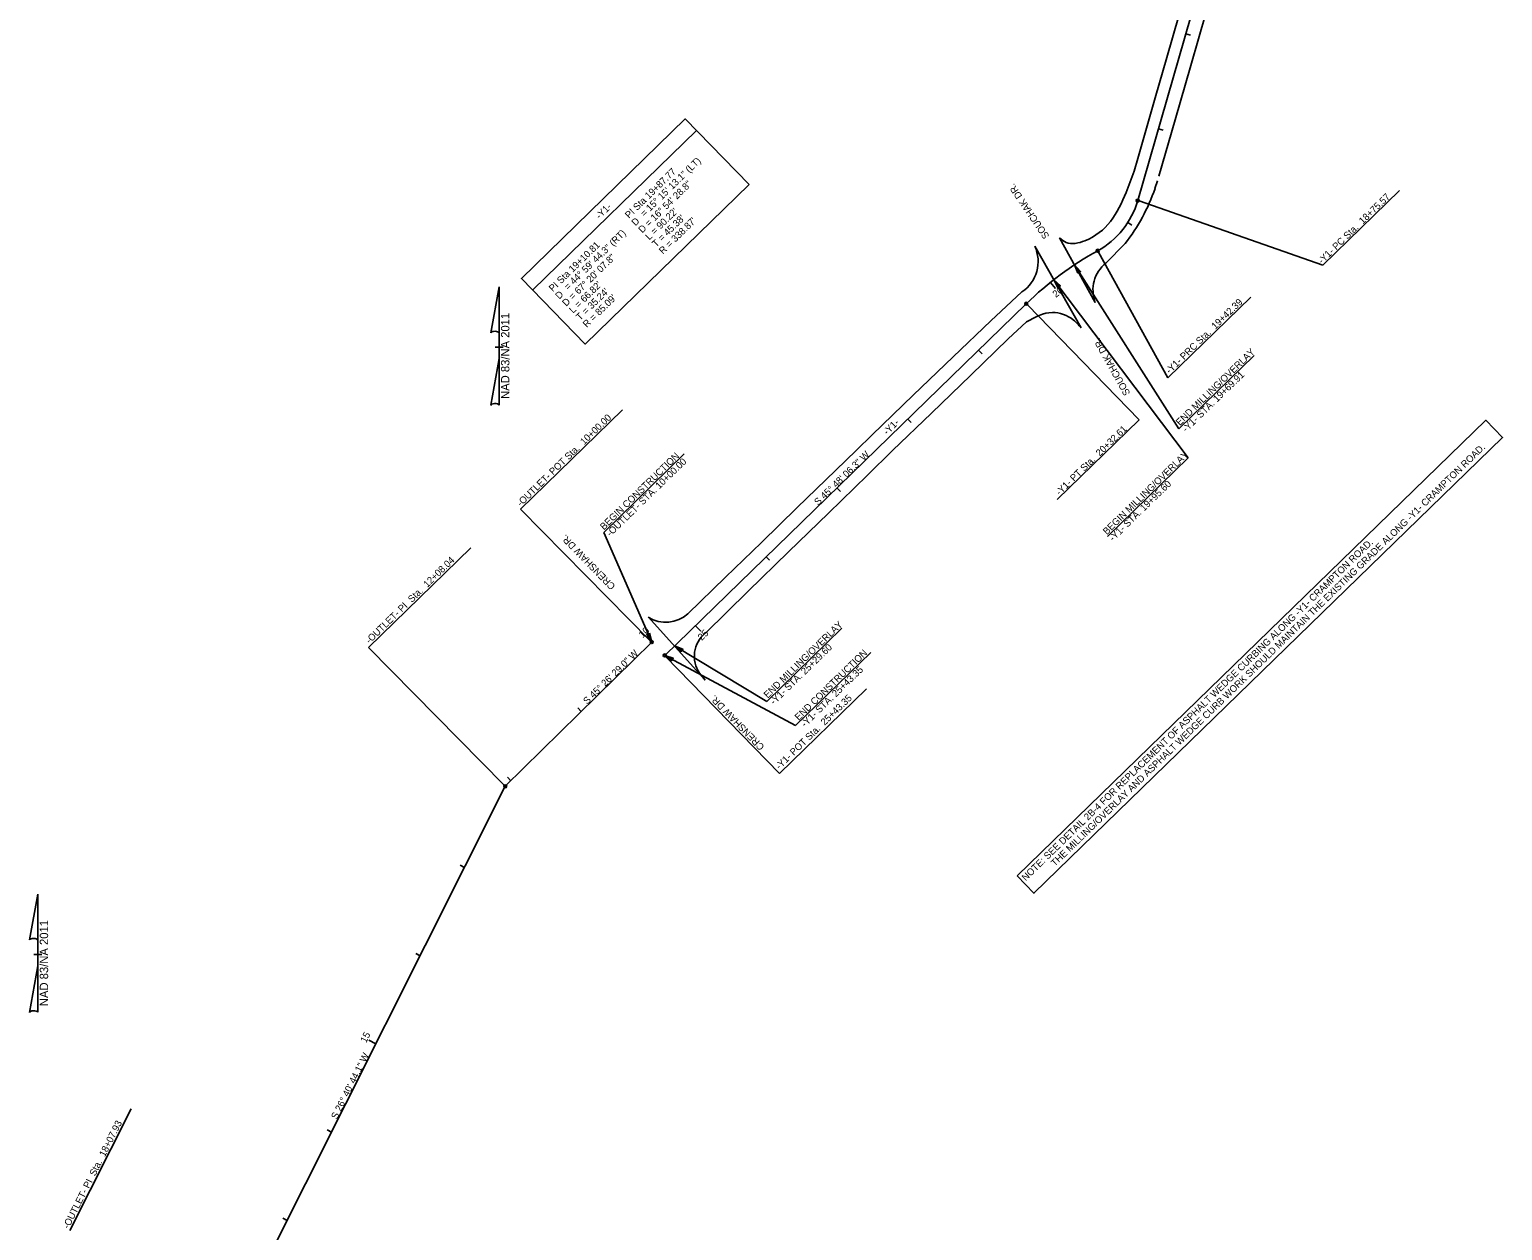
# Model space of a CAD drawing. Extents: x 2010838 to 2015151, y 441905 to 447792.
# Drawn here: x 2011071 to 2012563, y 443073 to 444289 of the extents above; entities that cross this region are included whole.
import ezdxf

# ---------------------------------------------------------------- set-up
doc = ezdxf.new("R2010")
doc.units = 0
for name, color, linetype in [('$AUDIT_BAD_LAYER1', 7, 'Continuous'), ('1-BUFFER', 7, 'Continuous'), ('B - Border Text', 7, 'Continuous'), ('C-Building', 7, 'Continuous'), ('C-EOP 1', 7, 'Continuous'), ('C-Grave Plots', 7, 'Continuous'), ('C-SHBD-TEXT', 7, 'Continuous'), ('CLRD', 7, 'Continuous'), ('Cont-10-Lidar', 7, 'Continuous'), ('Cont-2-Lidar', 7, 'Continuous'), ('Default_10ft_LIDAR_Contou', 7, 'Continuous'), ('Default_2FT_LIDAR_Contour', 7, 'Continuous'), ('Default_Parcels', 7, 'Continuous'), ('s-Existing Major', 7, 'Continuous'), ('S-Existing Minor', 7, 'Continuous'), ('S-overhead electric', 7, 'Continuous')]:
    doc.layers.add(name, color=color, linetype=linetype)

msp = doc.modelspace()

# ---------------------------------------------------------------- linework, layer by layer
at = {"layer": '$AUDIT_BAD_LAYER1'}
for p, q in [((2012370.9, 444732.8), (2012193.3, 444115.9)), ((2012080.5, 444011.4), (2011714.4, 443655.3))]:
    msp.add_line(p, q, dxfattribs=at)
for centre, radius, start, end in [((2012111.6, 444139.5), 85.1, 298.9446, 343.9402), ((2012316.8, 443768.5), 338.9, 118.9446, 134.1983)]:
    msp.add_arc(centre, radius, start, end, dxfattribs=at)
at = {"layer": '1-BUFFER'}
msp.add_lwpolyline([(2012071.2, 443432), (2012545.7, 443893.4), (2012562.7, 443875.9), (2012088.2, 443414.5)], close=True, dxfattribs=at)
at = {"layer": 'B - Border Text'}
for p, q in [((2011538.5, 443982.1), (2011546.7, 444028.4)), ((2011546.7, 444028.4), (2011546.7, 444028.4)), ((2011546.7, 444028.4), (2011546.7, 444028.4)), ((2011546.7, 444028.4), (2011546.7, 443980.6)), ((2011546.7, 443955.8), (2011546.7, 443982)), ((2011546.7, 443980.6), (2011546.7, 443982)), ((2011546.3, 443967.4), (2011542.7, 443967.4)), ((2011542.7, 443967.4), (2011542.7, 443967.4)), ((2011542.8, 443967.4), (2011550.8, 443967.4)), ((2011546.7, 443955.8), (2011538.4, 443908.6)), ((2011546.8, 443908.8), (2011546.7, 443955.8)), ((2011071.4, 443367.3), (2011079.6, 443413.6)), ((2011079.6, 443413.6), (2011079.6, 443413.6)), ((2011079.6, 443413.6), (2011079.6, 443413.6)), ((2011079.6, 443413.6), (2011079.6, 443365.8)), ((2011079.6, 443341), (2011079.6, 443367.2)), ((2011079.6, 443365.8), (2011079.6, 443367.2)), ((2011079.2, 443352.6), (2011075.6, 443352.6)), ((2011075.6, 443352.6), (2011075.6, 443352.6)), ((2011075.7, 443352.6), (2011083.7, 443352.6)), ((2011079.6, 443341), (2011071.3, 443293.8)), ((2011079.7, 443294), (2011079.6, 443341))]:
    msp.add_line(p, q, dxfattribs=at)
for centre, start_param, end_param in [((2011542.6, 443981.6), 0.216388, 2.908219), ((2011542.6, 443908.4), 0.201328, 3.141593), ((2011075.5, 443366.8), 0.216388, 2.908219), ((2011075.5, 443293.6), 0.201328, 3.141593)]:
    msp.add_ellipse(centre, major_axis=(4.23, -0.03), ratio=0.461098, start_param=start_param, end_param=end_param, dxfattribs=at)
at = {"layer": 'C-Building'}
for p, q in [((2012241.9, 444284.6), (2012246.7, 444283.2)), ((2012214.3, 444188.5), (2012219.1, 444187.2)), ((2012183.3, 444093.7), (2012187.5, 444091)), ((2012032.2, 443964.4), (2012035.7, 443960.8)), ((2011960.5, 443894.7), (2011964, 443891.1)), ((2011888.8, 443825), (2011892.3, 443821.4)), ((2011817.1, 443755.3), (2011820.6, 443751.7)), ((2011630, 443598.6), (2011626.5, 443602.2)), ((2011558.8, 443528.5), (2011555.2, 443532)), ((2011511.7, 443440.7), (2011507.3, 443442.9)), ((2011466.8, 443351.3), (2011462.4, 443353.6)), ((2011377, 443172.6), (2011372.6, 443174.9)), ((2011332.1, 443083.3), (2011327.7, 443085.5))]:
    msp.add_line(p, q, dxfattribs=at)
at = {"layer": 'C-EOP 1'}
for p, q in [((2012105, 444033), (2012110, 444026.7)), ((2011745.4, 443685.6), (2011751, 443679.8)), ((2011701.3, 443668.8), (2011695.6, 443674.5)), ((2011421.9, 443262), (2011414.8, 443265.6))]:
    msp.add_line(p, q, dxfattribs=at)
at = {"layer": 'C-SHBD-TEXT'}
for p, q in [((2012089.1, 444069.7), (2012136.1, 443987)), ((2012114, 444078.1), (2012150.3, 444012.8)), ((2011755.5, 443630.4), (2011697.9, 443694))]:
    msp.add_line(p, q, dxfattribs=at)
at = {"layer": 'CLRD'}
for p, q in [((2012370.9, 444732.8), (2012193.3, 444115.9)), ((2012080.5, 444011.4), (2011714.4, 443655.3)), ((2011701.3, 443668.8), (2011553, 443522.8)), ((2011553, 443522.8), (2011283.7, 442986.8))]:
    msp.add_line(p, q, dxfattribs=at)
for centre, radius, start, end in [((2012111.6, 444139.5), 85.1, 298.9446, 343.9402), ((2012316.8, 443768.5), 338.9, 118.9446, 134.1983)]:
    msp.add_arc(centre, radius, start, end, dxfattribs=at)
at = {"layer": 'Default_10ft_LIDAR_Contou'}
for p, q in [((2012380.9, 444050.5), (2012458.4, 444125.9)), ((2012194.8, 444115.5), (2012380.9, 444050.5)), ((2012153.5, 444063.7), (2012223.9, 443936.4)), ((2012081.6, 444010.3), (2012194.8, 443893.8)), ((2012307.9, 444018), (2012223.9, 443936.4)), ((2011568.6, 443803.5), (2011671.8, 443903.9)), ((2012111.8, 443813.1), (2012194.8, 443893.8)), ((2011700.2, 443669.9), (2011568.6, 443803.5)), ((2011414.6, 443663.4), (2011518.2, 443764.2)), ((2011552, 443523.9), (2011414.6, 443663.4)), ((2011715.4, 443654.3), (2011830.5, 443535.8)), ((2011830.5, 443535.8), (2011918.6, 443621.4)), ((2011112.2, 443073), (2011174.2, 443196.2))]:
    msp.add_line(p, q, dxfattribs=at)
for centre in [(2012193.3, 444115.9), (2012152.8, 444065), (2012080.5, 444011.4), (2011701.3, 443668.8), (2011714.4, 443655.3), (2011553, 443522.8)]:
    msp.add_circle(centre, 1.5, dxfattribs=at)
at = {"layer": 'Default_Parcels'}
msp.add_line((2011580.8, 444025.4), (2011746.7, 444186.7), dxfattribs=at)
msp.add_lwpolyline([(2011800, 444132), (2011634, 443970.6), (2011569.4, 444037.1), (2011735.3, 444198.5)], close=True, dxfattribs=at)
at = {"layer": 's-Existing Major'}
for points in [[(2012132.8, 444042.3), (2012129.2, 444050.7), (2012135.5, 444043.9), (2012133.5, 444044.1)], [(2012112.6, 444027.6), (2012108.4, 444035.7), (2012115.1, 444029.4), (2012113.2, 444029.4)], [(2011699.1, 443677.7), (2011701.3, 443668.8), (2011696.2, 443676.5), (2011698.1, 443676)], [(2011731.1, 443659), (2011724.2, 443664.9), (2011732.8, 443661.6), (2011731, 443660.9)], [(2011721.5, 443649.7), (2011714.4, 443655.3), (2011723.1, 443652.5), (2011721.3, 443651.6)]]:
    msp.add_lwpolyline(points, close=True, dxfattribs=at)
at = {"layer": 'S-Existing Minor'}
for p, q in [((2012129.2, 444050.7), (2012235, 443884.9)), ((2012108.4, 444035.7), (2012244.5, 443855.5)), ((2012235, 443884.9), (2012311.2, 443959)), ((2011652.7, 443779.9), (2011734.3, 443859.3)), ((2012162.6, 443775.9), (2012244.5, 443855.5)), ((2011701.3, 443668.8), (2011652.7, 443779.9)), ((2011817.7, 443608.8), (2011893.9, 443683)), ((2011724.2, 443664.9), (2011817.7, 443608.8)), ((2011714.4, 443655.3), (2011846.9, 443584.2)), ((2011846.9, 443584.2), (2011923.1, 443658.3))]:
    msp.add_line(p, q, dxfattribs=at)
at = {"layer": 'S-overhead electric'}
for p, q in [((2012193.3, 444158.4), (2012189.6, 444145.5)), ((2012189.6, 444145.5), (2012181.8, 444124.2)), ((2012210.8, 444128.1), (2012213.4, 444136)), ((2012136.1, 443987), (2012089.1, 444069.7)), ((2012114, 444078.1), (2012150.3, 444012.8)), ((2012161.2, 444052.6), (2012180.6, 444072.3)), ((2011908.6, 443863.2), (2011924.6, 443878.6)), ((2011919.7, 443837.8), (2011944.9, 443862.7)), ((2011755.5, 443630.4), (2011697.9, 443694)), ((2011749.8, 443637.2), (2011755.5, 443630.4))]:
    msp.add_line(p, q, dxfattribs=at)
for points in [[(2012214.8, 444140.6), (2012231.4, 444197.5), (2012247, 444252.5), (2012262.5, 444306.6), (2012277.8, 444361), (2012294.5, 444419.1), (2012308.1, 444465.5), (2012323.9, 444521.6), (2012337.3, 444572.2), (2012352.2, 444622.1), (2012368.4, 444674.4)], [(2012298.3, 444525.6), (2012284.2, 444475.2), (2012267.7, 444418.9), (2012251.3, 444361.5), (2012234.9, 444303), (2012222.7, 444260.8), (2012211.1, 444219.8), (2012193.3, 444158.4)], [(2012076.1, 444023.4), (2012044.6, 443994.1), (2012006.6, 443957.8), (2011966.1, 443918.8), (2011924.6, 443878.6)], [(2011944.9, 443862.7), (2011984.4, 443900.5), (2012024.4, 443939.1), (2012062.3, 443975.9), (2012080.8, 443993.2)], [(2011738, 443697.3), (2011775.9, 443734.4), (2011812.3, 443769.8), (2011848.7, 443805), (2011887.2, 443842.5), (2011908.6, 443863.2)], [(2011919.7, 443837.8), (2011880.3, 443799.5), (2011839.8, 443760.1), (2011798.8, 443720.5), (2011755.6, 443677.9)]]:
    msp.add_lwpolyline(points, dxfattribs=at)
for centre, major_axis, ratio, start_param, end_param in [((2012031.1, 444189.6), (63.2, 179.4), 0.998727, 4.386278, 4.721356), ((2012055.4, 444054.2), (-7.9, 36.3), 0.998589, 3.521091, 4.93017), ((2012183.1, 444025.2), (-34.8, 4.3), 0.999935, 5.51285, 6.768078), ((2011715.7, 443722.4), (11.4, -31.5), 0.999683, 5.3735, 6.662257), ((2011774.7, 443654.4), (-12.7, 27.5), 0.999754, 0.251551, 1.742312)]:
    msp.add_ellipse(centre, major_axis=major_axis, ratio=ratio, start_param=start_param, end_param=end_param, dxfattribs=at)
for points in [[(2012181.8, 444124.2), (2012165.8, 444094.8), (2012139.8, 444075.2), (2012120.9, 444073.5), (2012114, 444078.1)], [(2012080.8, 443993.2), (2012106.9, 444002.6), (2012128.1, 443995.1), (2012136.1, 443987)]]:
    msp.add_spline(points, degree=3, dxfattribs=at)

# ---------------------------------------------------------------- texts
at = {"layer": 'B - Border Text'}
for p in [(2011557.2, 443915), (2011090.2, 443300.2)]:
    msp.add_text('NAD 83/NA 2011', height=8.5, rotation=90, dxfattribs=at).set_placement(p)
at = {"layer": 'C-Grave Plots'}
for s, rotation, p in [('SOUCHAK DR.', 124.0802, (2012104.2, 444080)), ('SOUCHAK DR.', 119.164, (2012186, 443920.8)), ('END MILLING/OVERLAY', 44.1983, (2012236, 443887.5)), ('-Y1- STA. 19+69.91', 44.1983, (2012242.4, 443880.9)), ('BEGIN CONSTRUCTION', 44.1983, (2011653, 443781.8)), ('BEGIN MILLING/OVERLAY', 44.1983, (2012162.1, 443777)), ('-OUTLET- STA. 10+00.00', 44.1983, (2011659.4, 443775.2)), ('-Y1- STA. 19+95.60', 44.1983, (2012168.4, 443770.4)), ('CRENSHAW DR.', 134.169, (2011665, 443725.8)), ('END MILLING/OVERLAY', 44.1983, (2011818.7, 443611.5)), ('-Y1- STA. 25+29.60', 44.1983, (2011825.1, 443604.9)), ('END CONSTRUCTION', 44.1983, (2011850.1, 443588.9)), ('-Y1- STA. 25+43.35', 44.1983, (2011856.5, 443582.3)), ('CRENSHAW DR.', 134.169, (2011815.9, 443563.2))]:
    msp.add_text(s, height=7, rotation=rotation, dxfattribs=at).set_placement(p)
at = {"layer": 'Cont-10-Lidar'}
for s, p in [('THE MILLING/OVERLAY AND ASPHALT WEDGE CURB WORK SHOULD MAINTAIN THE EXISTING GRADE ALONG -Y1- CRAMPTON ROAD.', (2012109.5, 443441.2)), ('NOTE: SEE DETAIL 2B-4 FOR REPLACEMENT OF ASPHALT WEDGE CURBING ALONG -Y1- CRAMPTON ROAD.', (2012079.9, 443426.5))]:
    msp.add_text(s, height=7, rotation=44.1983, dxfattribs=at).set_placement(p)
at = {"layer": 'Cont-2-Lidar'}
for s, rotation, p in [('S 45%%d 48\' 06.3" W', 44.1983, (2011869.8, 443806.8)), ('S 45%%d 26\' 29.0" W', 44.5586, (2011636, 443605.3)), ('S 26%%d 40\' 44.1" W', 63.3211, (2011382.5, 443185.1))]:
    msp.add_text(s, height=7, rotation=rotation, dxfattribs=at).set_placement(p)
at = {"layer": 'Default_10ft_LIDAR_Contou'}
for s, rotation, p in [('-Y1- PC Sta.  18+75.57', 44.1983, (2012379.9, 444051.2)), ('-Y1- PRC Sta.  19+42.39', 44.1983, (2012225.7, 443940)), ('-OUTLET- POT Sta.  10+00.00', 44.1983, (2011568.7, 443805.6)), ('-Y1- PT Sta.  20+32.61', 44.1983, (2012114.3, 443816.9)), ('-OUTLET- PI  Sta.  12+08.04', 44.1983, (2011415.6, 443666.7)), ('-Y1- POT Sta.  25+43.35', 44.1983, (2011830.6, 443539.4)), ('-OUTLET- PI  Sta.  18+07.93', 63.277, (2011110.9, 443074.2))]:
    msp.add_text(s, height=7, rotation=rotation, dxfattribs=at).set_placement(p)
at = {"layer": 'Default_2FT_LIDAR_Contour'}
for s, rotation, p in [('20', 38.6853, (2012110.5, 444017.3)), ('-Y1-', 44.1983, (2011939.7, 443878.1)), ('10', 44.5586, (2011692.2, 443672.5)), ('25', 44.1983, (2011752, 443669.9)), ('15', 63.3211, (2011412.1, 443262.5))]:
    msp.add_text(s, height=7, rotation=rotation, dxfattribs=at).set_placement(p)
at = {"layer": 'Default_Parcels'}
for s, rotation, p in [('= 15%%d 15\' 13.1" (LT)', 44.3382, (2011693.8, 444098.9)), ('PI Sta 19+87.77', 44.3382, (2011678.3, 444097.3)), ('D = 16%%d 54\' 28.8"', 44.3382, (2011691.8, 444082.5)), ('-Y1-', 44.1983, (2011648.5, 444096.6)), ('D', 44.3382, (2011684.8, 444089.7)), ("L = 90.22'", 44.3382, (2011698.8, 444075.4)), ("T = 45.38'", 44.3382, (2011705.7, 444068.2)), ("R = 338.87'", 44.3382, (2011712.7, 444061.1)), ('= 44%%d 59\' 44.3" (RT)', 44.2472, (2011616.7, 444024.7)), ('PI Sta 19+10.81', 44.2472, (2011601.2, 444023.1)), ('D = 67%%d 20\' 07.8"', 44.2472, (2011614.7, 444008.3)), ('D', 44.2472, (2011607.7, 444015.5)), ("L = 66.82'", 44.2472, (2011621.7, 444001.2)), ("T = 35.24'", 44.2472, (2011628.7, 443994)), ("R = 85.09'", 44.2472, (2011635.6, 443986.8))]:
    msp.add_text(s, height=7, rotation=rotation, dxfattribs=at).set_placement(p)

doc.saveas('drawing.dxf')
